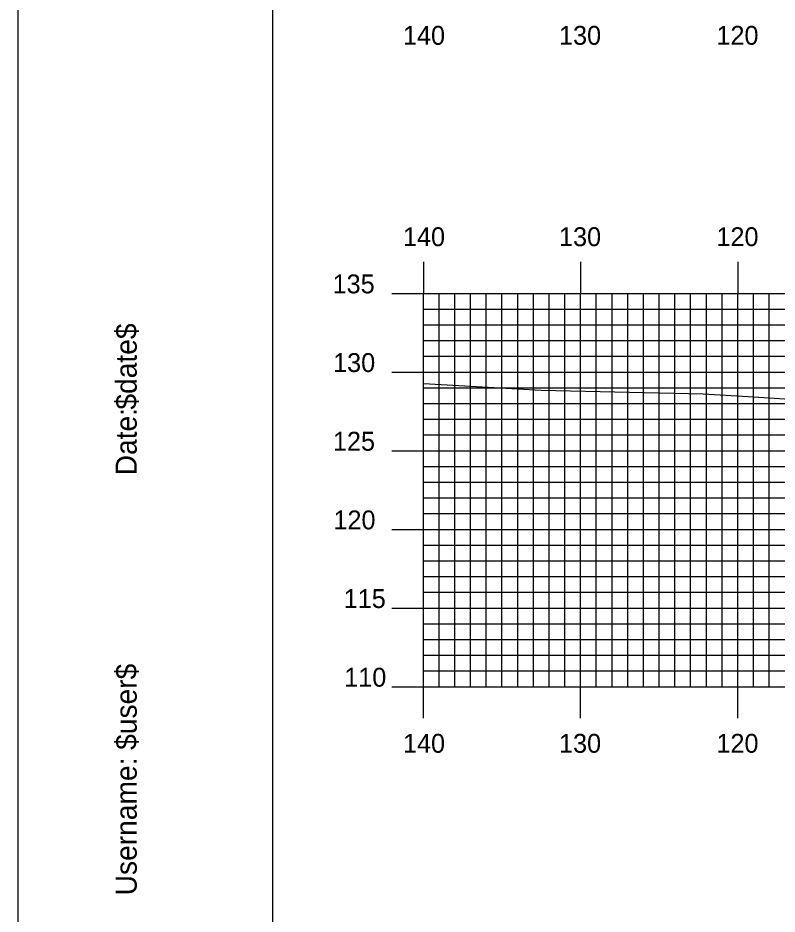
# Model space of a CAD drawing. Extents: x 1770842 to 1771185, y 442591 to 442811.
# Drawn here: x 1770841.8 to 1770890.1, y 442699.2 to 442756.2 of the extents above; entities that cross this region are included whole.
import ezdxf

# ---------------------------------------------------------------- set-up
doc = ezdxf.new("R2010")
doc.units = 0
for name, color, linetype in [('BORDER', 7, 'Continuous'), ('H_V ANNOTATION', 7, 'Continuous'), ('MAJOR', 7, 'Continuous'), ('MINOR', 7, 'Continuous'), ('PLOT BOUNDARY', 7, 'Continuous'), ('S_Roadway_Centerline', 7, 'Continuous')]:
    doc.layers.add(name, color=color, linetype=linetype)

msp = doc.modelspace()

# ---------------------------------------------------------------- linework, layer by layer
at = {"layer": 'BORDER'}
msp.add_lwpolyline([(1770857.954, 442596.665), (1771177.954, 442596.665), (1771177.954, 442806.665), (1770857.954, 442806.665)], close=True, dxfattribs=at)
at = {"layer": 'MAJOR'}
for p, q in [((1770867.554, 442740.669), (1770867.554, 442738.665)), ((1770877.554, 442740.669), (1770877.554, 442738.665)), ((1770887.554, 442740.669), (1770887.554, 442738.665)), ((1770865.55, 442738.665), (1770867.554, 442738.665)), ((1770867.554, 442738.665), (1771147.554, 442738.665)), ((1770867.554, 442713.665), (1770867.554, 442738.665)), ((1770867.554, 442713.665), (1770867.554, 442738.665)), ((1770867.554, 442738.665), (1771147.554, 442738.665)), ((1770877.554, 442713.665), (1770877.554, 442738.665)), ((1770887.554, 442713.665), (1770887.554, 442738.665)), ((1770865.55, 442733.665), (1770867.554, 442733.665)), ((1770867.554, 442733.665), (1771147.554, 442733.665)), ((1770865.55, 442728.665), (1770867.554, 442728.665)), ((1770867.554, 442728.665), (1771147.554, 442728.665)), ((1770865.55, 442723.665), (1770867.554, 442723.665)), ((1770867.554, 442723.665), (1771147.554, 442723.665)), ((1770865.55, 442718.665), (1770867.554, 442718.665)), ((1770867.554, 442718.665), (1771147.554, 442718.665)), ((1770865.55, 442713.665), (1770867.554, 442713.665)), ((1770867.554, 442713.665), (1771147.554, 442713.665)), ((1770867.554, 442713.665), (1771147.554, 442713.665)), ((1770867.554, 442711.661), (1770867.554, 442713.665)), ((1770877.554, 442711.661), (1770877.554, 442713.665)), ((1770887.554, 442711.661), (1770887.554, 442713.665))]:
    msp.add_line(p, q, dxfattribs=at)
at = {"layer": 'MINOR'}
for p, q in [((1770868.554, 442713.665), (1770868.554, 442738.665)), ((1770869.554, 442713.665), (1770869.554, 442738.665)), ((1770870.554, 442713.665), (1770870.554, 442738.665)), ((1770871.554, 442713.665), (1770871.554, 442738.665)), ((1770872.554, 442713.665), (1770872.554, 442738.665)), ((1770873.554, 442713.665), (1770873.554, 442738.665)), ((1770874.554, 442713.665), (1770874.554, 442738.665)), ((1770875.554, 442713.665), (1770875.554, 442738.665)), ((1770876.554, 442713.665), (1770876.554, 442738.665)), ((1770878.554, 442713.665), (1770878.554, 442738.665)), ((1770879.554, 442713.665), (1770879.554, 442738.665)), ((1770880.554, 442713.665), (1770880.554, 442738.665)), ((1770881.554, 442713.665), (1770881.554, 442738.665)), ((1770882.554, 442713.665), (1770882.554, 442738.665)), ((1770883.554, 442713.665), (1770883.554, 442738.665)), ((1770884.554, 442713.665), (1770884.554, 442738.665)), ((1770885.554, 442713.665), (1770885.554, 442738.665)), ((1770886.554, 442713.665), (1770886.554, 442738.665)), ((1770888.554, 442713.665), (1770888.554, 442738.665)), ((1770889.554, 442713.665), (1770889.554, 442738.665)), ((1770867.554, 442737.665), (1771147.554, 442737.665)), ((1770867.554, 442737.665), (1770869.558, 442737.665)), ((1770867.554, 442736.665), (1771147.554, 442736.665)), ((1770867.554, 442736.665), (1770869.558, 442736.665)), ((1770867.554, 442735.665), (1771147.554, 442735.665)), ((1770867.554, 442735.665), (1770869.558, 442735.665)), ((1770867.554, 442734.665), (1771147.554, 442734.665)), ((1770867.554, 442734.665), (1770869.558, 442734.665)), ((1770867.554, 442732.665), (1771147.554, 442732.665)), ((1770867.554, 442732.665), (1770869.558, 442732.665)), ((1770867.554, 442731.665), (1771147.554, 442731.665)), ((1770867.554, 442731.665), (1770869.558, 442731.665)), ((1770867.554, 442730.665), (1771147.554, 442730.665)), ((1770867.554, 442730.665), (1770869.558, 442730.665)), ((1770867.554, 442729.665), (1771147.554, 442729.665)), ((1770867.554, 442729.665), (1770869.558, 442729.665)), ((1770867.554, 442727.665), (1771147.554, 442727.665)), ((1770867.554, 442727.665), (1770869.558, 442727.665)), ((1770867.554, 442726.665), (1771147.554, 442726.665)), ((1770867.554, 442726.665), (1770869.558, 442726.665)), ((1770867.554, 442725.665), (1771147.554, 442725.665)), ((1770867.554, 442725.665), (1770869.558, 442725.665)), ((1770867.554, 442724.665), (1771147.554, 442724.665)), ((1770867.554, 442724.665), (1770869.558, 442724.665)), ((1770867.554, 442722.665), (1771147.554, 442722.665)), ((1770867.554, 442722.665), (1770869.558, 442722.665)), ((1770867.554, 442721.665), (1771147.554, 442721.665)), ((1770867.554, 442721.665), (1770869.558, 442721.665)), ((1770867.554, 442720.665), (1771147.554, 442720.665)), ((1770867.554, 442720.665), (1770869.558, 442720.665)), ((1770867.554, 442719.665), (1771147.554, 442719.665)), ((1770867.554, 442719.665), (1770869.558, 442719.665)), ((1770867.554, 442717.665), (1771147.554, 442717.665)), ((1770867.554, 442717.665), (1770869.558, 442717.665)), ((1770867.554, 442716.665), (1771147.554, 442716.665)), ((1770867.554, 442716.665), (1770869.558, 442716.665)), ((1770867.554, 442715.665), (1771147.554, 442715.665)), ((1770867.554, 442715.665), (1770869.558, 442715.665)), ((1770867.554, 442714.665), (1771147.554, 442714.665)), ((1770867.554, 442714.665), (1770869.558, 442714.665))]:
    msp.add_line(p, q, dxfattribs=at)
at = {"layer": 'PLOT BOUNDARY'}
msp.add_lwpolyline([(1770841.768, 442590.547), (1771181.768, 442590.547), (1771181.768, 442810.547), (1770841.768, 442810.547)], close=True, dxfattribs=at)
at = {"layer": 'S_Roadway_Centerline'}
msp.add_lwpolyline([(1770867.554, 442732.926), (1770875.047, 442732.521), (1770885.347, 442732.269), (1770888.578, 442732.094), (1770905.792, 442730.965), (1770910.229, 442730.845), (1770918.156, 442730.666), (1770922.756, 442730.55), (1770925.566, 442730.483), (1770933.687, 442729.93), (1770944.441, 442729.295)], dxfattribs=at)

# ---------------------------------------------------------------- texts
at = {"layer": 'BORDER'}
for s, p in [('$date$', (1770849.324, 442731.275)), ('Date:', (1770849.324, 442727.099)), ('$user$', (1770849.324, 442709.648)), ('Username:', (1770849.324, 442700.401))]:
    msp.add_text(s, height=1.3392, rotation=90, dxfattribs=at).set_placement(p)
at = {"layer": 'H_V ANNOTATION'}
for s, p in [('140', (1770866.259, 442754.465)), ('130', (1770876.184, 442754.465)), ('120', (1770886.195, 442754.465)), ('140', (1770866.259, 442741.665)), ('130', (1770876.184, 442741.665)), ('120', (1770886.195, 442741.665)), ('135', (1770861.782, 442738.665)), ('130', (1770861.814, 442733.665)), ('125', (1770861.803, 442728.665)), ('120', (1770861.835, 442723.665)), ('115', (1770862.489, 442718.665)), ('110', (1770862.521, 442713.665)), ('140', (1770866.259, 442709.465)), ('130', (1770876.184, 442709.465)), ('120', (1770886.195, 442709.465))]:
    msp.add_text(s, height=1.2, dxfattribs=at).set_placement(p)
at = {"layer": 'MAJOR'}
msp.add_text('-', height=0.012, dxfattribs=at).set_placement((1770867.545, 442713.665))

doc.saveas('drawing.dxf')
